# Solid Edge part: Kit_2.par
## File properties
Sűrűség: 0,000 kg/m^3
Pontosság: 0,990
Author: bmolnar
Last saved by: bmolnar
Revision: 76
Username: bmolnar
Dokumentum tartalom típus: 0
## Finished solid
Body 1: solid body, 23 faces, 39 edges, 29 vertices.
  Faces by surface: cylinder 10, plane 9, cone 3, torus 1
  Edges by curve: circle 25, line 14
Bounding box of the edges (mm; curved faces can reach further): 55.000 x 54.575 x 5.500, from (-27.5, -25.9, 0.7) to (27.5, 28.675, 6.2).
Cylindrical faces by radius (mm): R1.25 x2, R2.5 x4, R18.5 x1, R23.975 x1, R25.9 x1, R27.5 x1
Conical faces (half-angle, radius in mm at the cone's reference point): 45 deg R18 x1, 45 deg R25.8 x2
Toroidal faces (ring radius, tube radius in mm): R19.3 r0.8 x1
Planar faces by outward normal: +z 2, -z 5, oblique 2
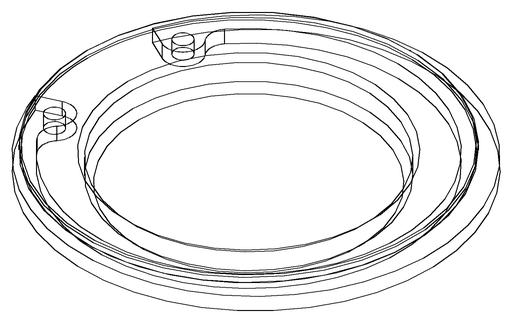
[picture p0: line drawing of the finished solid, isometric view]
